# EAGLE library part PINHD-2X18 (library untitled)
PIN HEADER
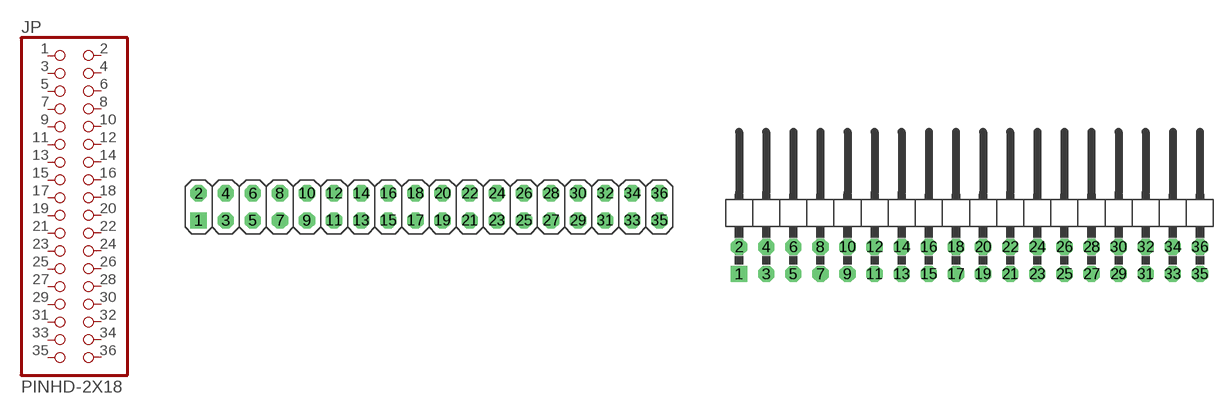
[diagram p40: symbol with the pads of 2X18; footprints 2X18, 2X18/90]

Designator prefix JP

## PINHD-2X18_2.54  [2X18]
1  1  pas
2  2  pas
3  3  pas
4  4  pas
5  5  pas
6  6  pas
7  7  pas
8  8  pas
9  9  pas
10  10  pas
11  11  pas
12  12  pas
13  13  pas
14  14  pas
15  15  pas
16  16  pas
17  17  pas
18  18  pas
19  19  pas
20  20  pas
21  21  pas
22  22  pas
23  23  pas
24  24  pas
25  25  pas
26  26  pas
27  27  pas
28  28  pas
29  29  pas
30  30  pas
31  31  pas
32  32  pas
33  33  pas
34  34  pas
35  35  pas
36  36  pas

## PINHD-2X18_2.54-90°  [2X18/90]
Pads as for 2X18

## PINHD-2X18_2.00  [2X18M]
Pads as for 2X18

## PINHD-2X18_2.54-SMD  [2X18SMD]
Pads as for 2X18

## PINHD-2X18_2.54-SMD-90°  [2X18SMD/90]
Pads as for 2X18

## Footprint 2X18 (pad centres in mm)
PIN HEADER - 2.54
drill 1.016 square: 1 -21.59,-1.27
drill 1.016 octagon: 2 -21.59,1.27; 3 -19.05,-1.27; 4 -19.05,1.27; 5 -16.51,-1.27; 6 -16.51,1.27; 7 -13.97,-1.27; 8 -13.97,1.27; 9 -11.43,-1.27; 10 -11.43,1.27; 11 -8.89,-1.27; 12 -8.89,1.27; 13 -6.35,-1.27; 14 -6.35,1.27; 15 -3.81,-1.27; 16 -3.81,1.27; 17 -1.27,-1.27; 18 -1.27,1.27; 19 1.27,-1.27; 20 1.27,1.27; 21 3.81,-1.27; 22 3.81,1.27; 23 6.35,-1.27; 24 6.35,1.27; 25 8.89,-1.27; 26 8.89,1.27; 27 11.43,-1.27; 28 11.43,1.27; 29 13.97,-1.27; 30 13.97,1.27; 31 16.51,-1.27; 32 16.51,1.27; 33 19.05,-1.27; 34 19.05,1.27; 35 21.59,-1.27; 36 21.59,1.27

## Footprint 2X18/90 (pad centres in mm)
PIN HEADER - 2.54 90°
drill 1.016 square: 1 -21.59,-6.35
drill 1.016 octagon: 2 -21.59,-3.81; 3 -19.05,-6.35; 4 -19.05,-3.81; 5 -16.51,-6.35; 6 -16.51,-3.81; 7 -13.97,-6.35; 8 -13.97,-3.81; 9 -11.43,-6.35; 10 -11.43,-3.81; 11 -8.89,-6.35; 12 -8.89,-3.81; 13 -6.35,-6.35; 14 -6.35,-3.81; 15 -3.81,-6.35; 16 -3.81,-3.81; 17 -1.27,-6.35; 18 -1.27,-3.81; 19 1.27,-6.35; 20 1.27,-3.81; 21 3.81,-6.35; 22 3.81,-3.81; 23 6.35,-6.35; 24 6.35,-3.81; 25 8.89,-6.35; 26 8.89,-3.81; 27 11.43,-6.35; 28 11.43,-3.81; 29 13.97,-6.35; 30 13.97,-3.81; 31 16.51,-6.35; 32 16.51,-3.81; 33 19.05,-6.35; 34 19.05,-3.81; 35 21.59,-6.35; 36 21.59,-3.81

## Footprint 2X18M (pad centres in mm)
PIN HEADER - 2
drill 0.914 square: 1 -17,-1
drill 0.914 round: 2 -17,1; 3 -15,-1; 4 -15,1; 5 -13,-1; 6 -13,1; 7 -11,-1; 8 -11,1; 9 -9,-1; 10 -9,1; 11 -7,-1; 12 -7,1; 13 -5,-1; 14 -5,1; 15 -3,-1; 16 -3,1; 17 -1,-1; 18 -1,1; 19 1,-1; 20 1,1; 21 3,-1; 22 3,1; 23 5,-1; 24 5,1; 25 7,-1; 26 7,1; 27 9,-1; 28 9,1; 29 11,-1; 30 11,1; 31 13,-1; 32 13,1; 33 15,-1; 34 15,1; 35 17,-1; 36 17,1

## Footprint 2X18SMD (pad centres in mm)
PIN HEADER - 2.54 SMD
smd 1.016 x 3.302: 1 -1.27,-3.81; 2 -1.27,1.27; 3 1.27,-3.81; 4 1.27,1.27; 5 3.81,-3.81; 6 3.81,1.27; 7 6.35,-3.81; 8 6.35,1.27; 9 8.89,-3.81; 10 8.89,1.27; 11 11.43,-3.81; 12 11.43,1.27; 13 13.97,-3.81; 14 13.97,1.27; 15 16.51,-3.81; 16 16.51,1.27; 17 19.05,-3.81; 18 19.05,1.27; 19 21.59,-3.81; 20 21.59,1.27; 21 24.13,-3.81; 22 24.13,1.27; 23 26.67,-3.81; 24 26.67,1.27; 25 29.21,-3.81; 26 29.21,1.27; 27 31.75,-3.81; 28 31.75,1.27; 29 34.29,-3.81; 30 34.29,1.27; 31 36.83,-3.81; 32 36.83,1.27; 33 39.37,-3.81; 34 39.37,1.27; 35 41.91,-3.81; 36 41.91,1.27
